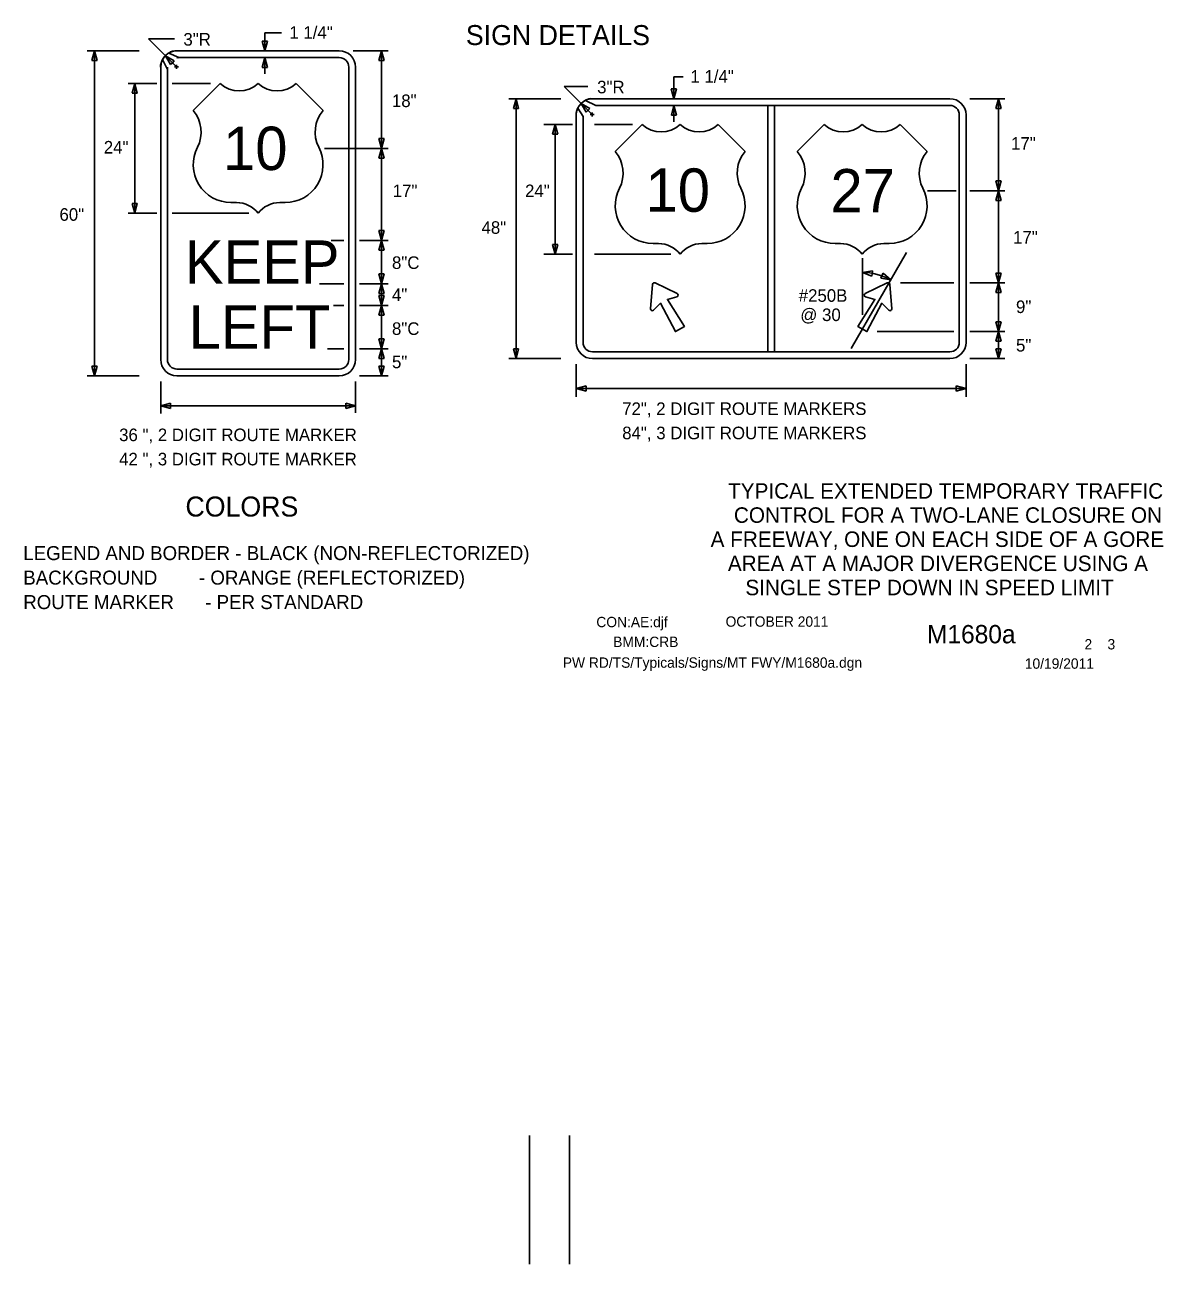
# Model space of a CAD drawing. Extents: x 16486 to 19505, y 5576 to 6998.
# Drawn here: x 17777 to 18460, y 5576 to 6320 of the extents above; entities that cross this region are included whole.
import ezdxf

# ---------------------------------------------------------------- set-up
doc = ezdxf.new("R2010")
doc.units = 0
for name, color, linetype in [('ALI_LEGAL_EX', 7, 'Continuous'), ('BORDER', 7, 'Continuous'), ('BORDER_SIGNAL_WO', 7, 'Continuous'), ('TRAFFIC_SIGNS_PR', 7, 'Continuous'), ('TYPICAL_EX', 7, 'Continuous'), ('TYPICAL_TEXT_DIMEN_PR', 7, 'Continuous')]:
    doc.layers.add(name, color=color, linetype=linetype)

msp = doc.modelspace()

# ---------------------------------------------------------------- linework, layer by layer
at = {"layer": 'ALI_LEGAL_EX'}
for p, q in [((18079.61, 5652.91), (18079.61, 5575.75)), ((18103.61, 5652.91), (18103.61, 5575.75))]:
    msp.add_line(p, q, dxfattribs=at)
at = {"layer": 'TRAFFIC_SIGNS_PR'}
for p, q in [((17860.3, 6300.32), (17859.29, 6298.82)), ((17869.08, 6299.88), (17862.99, 6302.62)), ((17867.88, 6303.94), (17965.38, 6303.94)), ((17858.13, 6118.69), (17858.13, 6294.19)), ((17859.32, 6298.74), (17862.19, 6292.7)), ((17862.19, 6294.19), (17862.19, 6118.69)), ((17965.38, 6299.88), (17867.88, 6299.88)), ((17971.06, 6118.69), (17971.06, 6294.19)), ((17975.13, 6294.19), (17975.13, 6118.69)), ((18119.35, 6271.19), (18113.12, 6274.21)), ((18117.4, 6275.24), (18331.9, 6275.24)), ((18117.4, 6275.24), (18331.9, 6275.24)), ((18119.34, 6271.18), (18222.62, 6271.18)), ((18331.9, 6271.18), (18119.34, 6271.18)), ((18222.62, 6271.18), (18222.62, 6123.31)), ((18226.68, 6271.18), (18226.68, 6123.31)), ((18226.68, 6271.18), (18331.9, 6271.18)), ((18107.65, 6265.49), (18107.65, 6128.99)), ((18107.65, 6128.99), (18107.65, 6265.49)), ((18108.57, 6269.5), (18111.71, 6264.46)), ((18111.71, 6264.44), (18111.71, 6128.99)), ((18111.71, 6264.44), (18111.71, 6128.99)), ((18337.59, 6265.49), (18337.59, 6219.74)), ((18337.59, 6128.99), (18337.59, 6265.49)), ((18341.65, 6265.49), (18341.65, 6128.99)), ((18341.65, 6265.49), (18341.65, 6128.99)), ((18337.59, 6219.74), (18337.59, 6128.99)), ((18152.25, 6149.1), (18153.4, 6163.82)), ((18154.91, 6164.69), (18168.23, 6158.33)), ((18294.38, 6164.69), (18281.07, 6158.33)), ((18297.05, 6149.1), (18295.9, 6163.82)), ((18117.4, 6123.31), (18331.9, 6123.31)), ((18117.4, 6119.24), (18331.9, 6119.24)), ((18331.9, 6119.24), (18117.4, 6119.24)), ((17867.88, 6113), (17965.38, 6113)), ((17965.38, 6108.94), (17867.88, 6108.94))]:
    msp.add_line(p, q, dxfattribs=at)
for points in [[(18119.34, 6271.18), (18119.32, 6271.19)], [(18111.71, 6264.46), (18111.71, 6264.44)], [(18168.07, 6156.36), (18162.34, 6154.78), (18172.56, 6138.61), (18167.16, 6135.49), (18158.27, 6152.43), (18154.04, 6148.26)], [(18281.23, 6156.36), (18286.96, 6154.78), (18276.74, 6138.61), (18282.14, 6135.49), (18291.03, 6152.43), (18295.26, 6148.26)]]:
    msp.add_lwpolyline(points, dxfattribs=at)
msp.add_lwpolyline([(18222.62, 6271.18), (18226.68, 6271.18), (18226.68, 6123.31), (18222.62, 6123.31)], close=True, dxfattribs=at)
for centre, radius, start, end in [((17867.88, 6294.19), 9.75, 90, 180), ((17867.29, 6296.37), 7.6, 85.58319, 124.53531), ((17965.38, 6294.19), 9.75, 0, 90), ((17865.16, 6294.78), 7.06, 145.86811, 184.82317), ((17856.73, 6293.45), 5.51, 352.24294, 7.75653), ((17868.48, 6304.31), 4.47, 262.2432, 277.7568), ((17965.38, 6294.19), 5.69, 0, 90), ((18117.4, 6265.49), 9.75, 90, 180), ((18117.4, 6265.49), 9.75, 90, 180), ((18116.72, 6268.68), 6.6, 84.11162, 123.06374), ((18118.34, 6278.36), 7.24, 277.81035, 278.05403), ((18331.9, 6265.49), 9.75, 0, 90), ((18331.9, 6265.49), 9.75, 0, 90), ((18331.9, 6265.49), 5.69, 0, 89.99421), ((18331.9, 6265.49), 5.69, 0, 90), ((18113.78, 6266.2), 6.17, 147.60925, 186.56283), ((18154.46, 6163.73), 1.06, 64.48226, 175.51774), ((18294.84, 6163.73), 1.06, 4.48226, 115.51774), ((18167.77, 6157.38), 1.06, 285.9885, 64.48226), ((18281.53, 6157.38), 1.06, 115.51774, 254.0115), ((18153.31, 6149.02), 1.06, 175.51775, 314.01151), ((18295.99, 6149.02), 1.06, 225.98849, 4.48225), ((18117.4, 6128.99), 9.75, 180, 270), ((18117.4, 6128.99), 9.75, 180, 270), ((18117.4, 6128.99), 5.69, 180, 270), ((18117.4, 6128.99), 5.69, 180, 270), ((18331.9, 6128.99), 9.75, 270, 0), ((18331.9, 6128.99), 5.69, 270, 0), ((18331.9, 6128.99), 9.75, 270, 0), ((18331.9, 6128.99), 5.69, 270, 0), ((17867.88, 6118.69), 9.75, 180, 270), ((17867.88, 6118.69), 5.69, 180, 270), ((17965.38, 6118.69), 5.69, 270, 0), ((17965.38, 6118.69), 9.75, 270, 0)]:
    msp.add_arc(centre, radius, start, end, dxfattribs=at)
at = {"layer": 'TYPICAL_EX'}
for p, q in [((17877.63, 6268.19), (17893.88, 6284.44)), ((17955.63, 6268.19), (17939.38, 6284.44)), ((18131.01, 6243.58), (18147.26, 6259.83)), ((18209.01, 6243.58), (18192.76, 6259.83)), ((18240.29, 6243.58), (18256.54, 6259.83)), ((18318.29, 6243.58), (18302.04, 6259.83)), ((17900.35, 6212.9), (17903.6, 6212.9)), ((17932.9, 6212.9), (17929.65, 6212.9)), ((18153.74, 6188.29), (18156.99, 6188.29)), ((18186.28, 6188.29), (18183.03, 6188.29)), ((18263.01, 6188.29), (18266.26, 6188.29)), ((18295.56, 6188.29), (18292.31, 6188.29))]:
    msp.add_line(p, q, dxfattribs=at)
for centre, radius, start, end in [((17905.25, 6296.28), 16.42, 226.14041, 313.85958), ((17928, 6296.28), 16.42, 226.14042, 313.85959), ((17862.23, 6255.18), 20.16, 333.09768, 40.19361), ((17971.03, 6255.18), 20.16, 139.80639, 206.90233), ((18158.64, 6271.67), 16.42, 226.14041, 313.85958), ((18181.39, 6271.67), 16.42, 226.14042, 313.85959), ((18267.91, 6271.67), 16.42, 226.14041, 313.85958), ((18290.66, 6271.67), 16.42, 226.14042, 313.85959), ((17900.4, 6235.63), 22.73, 152.6698, 269.90132), ((17932.86, 6235.63), 22.73, 270.09868, 27.3302), ((18115.61, 6230.57), 20.16, 333.09768, 40.19361), ((18224.41, 6230.57), 20.16, 139.80639, 206.90233), ((18224.89, 6230.57), 20.16, 333.09768, 40.19361), ((18333.69, 6230.57), 20.16, 139.80639, 206.90233), ((18153.78, 6211.02), 22.73, 152.6698, 269.90132), ((18186.24, 6211.02), 22.73, 270.09868, 27.3302), ((18263.06, 6211.02), 22.73, 152.6698, 269.90132), ((18295.52, 6211.02), 22.73, 270.09868, 27.3302), ((17903.65, 6196.62), 16.28, 37.1038, 90.13853), ((17929.61, 6196.62), 16.28, 89.86147, 142.8962), ((18157.03, 6172.01), 16.28, 37.1038, 90.13853), ((18182.99, 6172.01), 16.28, 89.86147, 142.8962), ((18266.31, 6172.01), 16.28, 37.1038, 90.13853), ((18292.27, 6172.01), 16.28, 89.86147, 142.8962)]:
    msp.add_arc(centre, radius, start, end, dxfattribs=at)
at = {"layer": 'TYPICAL_TEXT_DIMEN_PR'}
for p, q in [((17866.5, 6311.23), (17850.84, 6311.23)), ((17850.84, 6311.23), (17861.08, 6300.99)), ((17920.6, 6303.94), (17919.03, 6309.8)), ((17919.03, 6309.8), (17920.6, 6309.8)), ((17920.6, 6314.7), (17920.6, 6303.94)), ((17920.6, 6314.7), (17930.71, 6314.7)), ((17920.6, 6309.8), (17922.17, 6309.8)), ((17922.17, 6309.8), (17920.6, 6303.94)), ((17845.3, 6303.94), (17814, 6303.94)), ((17816.77, 6298.08), (17818.34, 6303.94)), ((17818.34, 6303.94), (17818.34, 6108.94)), ((17818.34, 6303.94), (17819.91, 6298.08)), ((17861.08, 6300.99), (17867.64, 6294.43)), ((17864.11, 6295.73), (17861.08, 6300.99)), ((17861.08, 6300.99), (17866.33, 6297.95)), ((17973.67, 6303.94), (17994.63, 6303.94)), ((17989.16, 6298.08), (17990.73, 6303.94)), ((17990.73, 6303.94), (17990.73, 6245.44)), ((17990.73, 6303.94), (17992.3, 6298.08)), ((17818.34, 6298.08), (17816.77, 6298.08)), ((17819.91, 6298.08), (17818.34, 6298.08)), ((17865.22, 6296.84), (17864.11, 6295.73)), ((17866.33, 6297.95), (17865.22, 6296.84)), ((17866.43, 6294.43), (17868.85, 6294.43)), ((17867.64, 6293.22), (17867.64, 6295.64)), ((17919.08, 6294.02), (17920.65, 6299.88)), ((17920.65, 6294.02), (17919.08, 6294.02)), ((17920.65, 6299.88), (17920.65, 6290.13)), ((17920.65, 6299.88), (17922.22, 6294.02)), ((17922.22, 6294.02), (17920.65, 6294.02)), ((17990.73, 6298.08), (17989.16, 6298.08)), ((17992.3, 6298.08), (17990.73, 6298.08)), ((18166.26, 6288.4), (18166.26, 6275.24)), ((18166.26, 6288.4), (18171.78, 6288.4)), ((17855.76, 6284.44), (17838.63, 6284.44)), ((17840.95, 6278.58), (17842.52, 6284.44)), ((17842.52, 6278.58), (17840.95, 6278.58)), ((17842.52, 6284.44), (17842.52, 6206.44)), ((17842.52, 6284.44), (17844.1, 6278.58)), ((17844.1, 6278.58), (17842.52, 6278.58)), ((17887.99, 6284.44), (17865.12, 6284.44)), ((18114.54, 6282.53), (18100.36, 6282.53)), ((18100.36, 6282.53), (18110.51, 6272.38)), ((18166.26, 6275.24), (18164.69, 6281.11)), ((18164.69, 6281.11), (18166.26, 6281.11)), ((18166.26, 6281.11), (18167.83, 6281.11)), ((18167.83, 6281.11), (18166.26, 6275.24)), ((18098.42, 6275.24), (18067.12, 6275.24)), ((18069.89, 6269.38), (18071.46, 6275.24)), ((18071.46, 6275.24), (18071.46, 6119.24)), ((18071.46, 6275.24), (18073.03, 6269.38)), ((18110.51, 6272.38), (18117.16, 6265.73)), ((18113.55, 6267.12), (18110.51, 6272.38)), ((18110.51, 6272.38), (18115.77, 6269.35)), ((18164.74, 6265.32), (18166.31, 6271.18)), ((18164.74, 6265.32), (18166.31, 6271.18)), ((18166.31, 6271.18), (18166.31, 6261.43)), ((18166.31, 6271.18), (18167.88, 6265.32)), ((18166.31, 6271.18), (18167.88, 6265.32)), ((18344.02, 6275.24), (18364.98, 6275.24)), ((18359.51, 6269.38), (18361.08, 6275.24)), ((18361.08, 6275.24), (18361.08, 6219.99)), ((18361.08, 6275.24), (18362.66, 6269.38)), ((18071.46, 6269.38), (18069.89, 6269.38)), ((18073.03, 6269.38), (18071.46, 6269.38)), ((18114.66, 6268.23), (18113.55, 6267.12)), ((18115.77, 6269.35), (18114.66, 6268.23)), ((18115.95, 6265.73), (18118.37, 6265.73)), ((18117.16, 6264.53), (18117.16, 6266.94)), ((18166.31, 6265.32), (18164.74, 6265.32)), ((18166.31, 6265.32), (18164.74, 6265.32)), ((18167.88, 6265.32), (18166.31, 6265.32)), ((18167.88, 6265.32), (18166.31, 6265.32)), ((18361.08, 6269.38), (18359.51, 6269.38)), ((18362.66, 6269.38), (18361.08, 6269.38)), ((18105.28, 6259.83), (18088.15, 6259.83)), ((18093.45, 6253.97), (18095.02, 6259.83)), ((18095.02, 6259.83), (18095.02, 6181.83)), ((18095.02, 6259.83), (18096.59, 6253.97)), ((18141.38, 6259.83), (18118.5, 6259.83)), ((17990.73, 6245.44), (17989.16, 6251.3)), ((17989.16, 6251.3), (17990.73, 6251.3)), ((17990.73, 6251.3), (17992.3, 6251.3)), ((17992.3, 6251.3), (17990.73, 6245.44)), ((18095.02, 6253.97), (18093.45, 6253.97)), ((18096.59, 6253.97), (18095.02, 6253.97)), ((17956.52, 6245.44), (17994.63, 6245.44)), ((17989.16, 6239.58), (17990.73, 6245.44)), ((17990.73, 6245.44), (17990.73, 6190.19)), ((17990.73, 6245.44), (17992.3, 6239.58)), ((17990.73, 6239.58), (17989.16, 6239.58)), ((17992.3, 6239.58), (17990.73, 6239.58)), ((18318.46, 6219.99), (18335.62, 6219.99)), ((18344.02, 6219.99), (18364.98, 6219.99)), ((18361.08, 6219.99), (18359.51, 6225.86)), ((18359.51, 6225.86), (18361.08, 6225.86)), ((18359.51, 6214.13), (18361.08, 6219.99)), ((18361.08, 6225.86), (18362.66, 6225.86)), ((18362.66, 6225.86), (18361.08, 6219.99)), ((18361.08, 6219.99), (18361.08, 6164.74)), ((18361.08, 6219.99), (18362.66, 6214.13)), ((17842.52, 6206.44), (17840.95, 6212.3)), ((17840.95, 6212.3), (17842.52, 6212.3)), ((17842.52, 6212.3), (17844.1, 6212.3)), ((17844.1, 6212.3), (17842.52, 6206.44)), ((18361.08, 6214.13), (18359.51, 6214.13)), ((18362.66, 6214.13), (18361.08, 6214.13)), ((17855.76, 6206.44), (17838.63, 6206.44)), ((17911.12, 6206.44), (17865.12, 6206.44)), ((17960.46, 6190.19), (17968.14, 6190.19)), ((17977.5, 6190.19), (17994.63, 6190.19)), ((17990.73, 6190.19), (17989.16, 6196.05)), ((17989.16, 6196.05), (17990.73, 6196.05)), ((17989.16, 6184.33), (17990.73, 6190.19)), ((17990.73, 6196.05), (17992.3, 6196.05)), ((17992.3, 6196.05), (17990.73, 6190.19)), ((17990.73, 6190.19), (17990.73, 6164.19)), ((17990.73, 6190.19), (17992.3, 6184.33)), ((17990.73, 6184.33), (17989.16, 6184.33)), ((17992.3, 6184.33), (17990.73, 6184.33)), ((18105.28, 6181.83), (18088.15, 6181.83)), ((18095.02, 6181.83), (18093.45, 6187.69)), ((18093.45, 6187.69), (18095.02, 6187.69)), ((18095.02, 6187.69), (18096.59, 6187.69)), ((18096.59, 6187.69), (18095.02, 6181.83)), ((18164.5, 6181.83), (18118.5, 6181.83)), ((18272.68, 6125.34), (18305.92, 6182.93)), ((18279.44, 6145.5), (18279.44, 6179.49)), ((17990.73, 6164.19), (17989.16, 6170.05)), ((17989.16, 6170.05), (17990.73, 6170.05)), ((17990.73, 6170.05), (17992.3, 6170.05)), ((17992.3, 6170.05), (17990.73, 6164.19)), ((18279.47, 6170.94), (18285.46, 6171.9)), ((18285.14, 6168.77), (18279.47, 6170.94)), ((18285.3, 6170.33), (18285.14, 6168.77)), ((18285.46, 6171.9), (18285.3, 6170.33)), ((18290.45, 6167.61), (18291.14, 6169.03)), ((18296.42, 6166.48), (18290.45, 6167.61)), ((18291.14, 6169.03), (18291.82, 6170.44)), ((18291.82, 6170.44), (18296.42, 6166.48)), ((18361.08, 6164.74), (18359.51, 6170.61)), ((18359.51, 6170.61), (18361.08, 6170.61)), ((18361.08, 6170.61), (18362.66, 6170.61)), ((18362.66, 6170.61), (18361.08, 6164.74)), ((17953.44, 6164.19), (17968.14, 6164.19)), ((17977.5, 6164.19), (17994.63, 6164.19)), ((17989.16, 6158.33), (17990.73, 6164.19)), ((17990.73, 6164.19), (17990.73, 6151.19)), ((17990.73, 6164.19), (17992.3, 6158.33)), ((18302.39, 6164.74), (18334.26, 6164.74)), ((18344.02, 6164.74), (18364.98, 6164.74)), ((18359.51, 6158.88), (18361.08, 6164.74)), ((18361.08, 6164.74), (18361.08, 6135.49)), ((18361.08, 6164.74), (18362.66, 6158.88)), ((17990.73, 6158.33), (17989.16, 6158.33)), ((17990.73, 6151.19), (17989.16, 6157.05)), ((17989.16, 6157.05), (17990.73, 6157.05)), ((17992.3, 6158.33), (17990.73, 6158.33)), ((17990.73, 6157.05), (17992.3, 6157.05)), ((17992.3, 6157.05), (17990.73, 6151.19)), ((18361.08, 6158.88), (18359.51, 6158.88)), ((18362.66, 6158.88), (18361.08, 6158.88)), ((17961.79, 6151.19), (17968.14, 6151.19)), ((17977.5, 6151.19), (17994.63, 6151.19)), ((17989.16, 6145.33), (17990.73, 6151.19)), ((17990.73, 6145.33), (17989.16, 6145.33)), ((17990.73, 6151.19), (17990.73, 6125.19)), ((17990.73, 6151.19), (17992.3, 6145.33)), ((17992.3, 6145.33), (17990.73, 6145.33)), ((18361.08, 6135.49), (18359.51, 6141.36)), ((18359.51, 6141.36), (18361.08, 6141.36)), ((18361.08, 6141.36), (18362.66, 6141.36)), ((18362.66, 6141.36), (18361.08, 6135.49)), ((17990.73, 6125.19), (17989.16, 6131.05)), ((17989.16, 6131.05), (17990.73, 6131.05)), ((17990.73, 6131.05), (17992.3, 6131.05)), ((17992.3, 6131.05), (17990.73, 6125.19)), ((18288.26, 6135.49), (18334.26, 6135.49)), ((18344.02, 6135.49), (18364.98, 6135.49)), ((18359.51, 6129.63), (18361.08, 6135.49)), ((18361.08, 6129.63), (18359.51, 6129.63)), ((18361.08, 6135.49), (18361.08, 6119.24)), ((18361.08, 6135.49), (18362.66, 6129.63)), ((18362.66, 6129.63), (18361.08, 6129.63)), ((17958.29, 6125.19), (17968.14, 6125.19)), ((17977.5, 6125.19), (17994.63, 6125.19)), ((17989.16, 6119.33), (17990.73, 6125.19)), ((17990.73, 6125.19), (17990.73, 6108.94)), ((17990.73, 6125.19), (17992.3, 6119.33)), ((18071.46, 6119.24), (18069.89, 6125.11)), ((18069.89, 6125.11), (18071.46, 6125.11)), ((18071.46, 6125.11), (18073.03, 6125.11)), ((18073.03, 6125.11), (18071.46, 6119.24)), ((18361.08, 6119.24), (18359.51, 6125.11)), ((18359.51, 6125.11), (18361.08, 6125.11)), ((18361.08, 6125.11), (18362.66, 6125.11)), ((18362.66, 6125.11), (18361.08, 6119.24)), ((17818.34, 6108.94), (17816.77, 6114.8)), ((17816.77, 6114.8), (17818.34, 6114.8)), ((17818.34, 6114.8), (17819.91, 6114.8)), ((17819.91, 6114.8), (17818.34, 6108.94)), ((17990.73, 6119.33), (17989.16, 6119.33)), ((17990.73, 6108.94), (17989.16, 6114.8)), ((17989.16, 6114.8), (17990.73, 6114.8)), ((17992.3, 6119.33), (17990.73, 6119.33)), ((17990.73, 6114.8), (17992.3, 6114.8)), ((17992.3, 6114.8), (17990.73, 6108.94)), ((18098.42, 6119.24), (18067.12, 6119.24)), ((18107.65, 6115.9), (18107.65, 6096.34)), ((18341.65, 6115.9), (18341.65, 6096.34)), ((18344.02, 6119.24), (18361.15, 6119.24)), ((18344.02, 6119.24), (18364.98, 6119.24)), ((18344.02, 6119.24), (18361.15, 6119.24)), ((17845.3, 6108.94), (17814, 6108.94)), ((17977.5, 6108.94), (17994.63, 6108.94)), ((17858.13, 6105.6), (17858.13, 6086.24)), ((17975.13, 6105.6), (17975.13, 6086.7)), ((18107.65, 6101.27), (18113.51, 6102.84)), ((18107.65, 6101.27), (18341.65, 6101.27)), ((18113.51, 6099.7), (18107.65, 6101.27)), ((18113.51, 6102.84), (18113.51, 6101.27)), ((18113.51, 6101.27), (18113.51, 6099.7)), ((18335.79, 6101.27), (18335.79, 6102.84)), ((18335.79, 6102.84), (18341.65, 6101.27)), ((18341.65, 6101.27), (18335.79, 6099.7)), ((18335.79, 6099.7), (18335.79, 6101.27)), ((17858.13, 6090.97), (17863.99, 6092.54)), ((17863.99, 6092.54), (17863.99, 6090.97)), ((17969.27, 6090.97), (17969.27, 6092.54)), ((17969.27, 6092.54), (17975.13, 6090.97)), ((17858.13, 6090.97), (17975.13, 6090.97)), ((17863.99, 6089.4), (17858.13, 6090.97)), ((17863.99, 6090.97), (17863.99, 6089.4)), ((17975.13, 6090.97), (17969.27, 6089.4)), ((17969.27, 6089.4), (17969.27, 6090.97))]:
    msp.add_line(p, q, dxfattribs=at)
msp.add_arc((18279.63, 6136.5), 34.39, 60.74521, 90.32117, dxfattribs=at)

# ---------------------------------------------------------------- texts
at = {"layer": 'BORDER'}
for s, p in [('TYPICAL EXTENDED TEMPORARY TRAFFIC', (18198.78, 6035.19)), ('CONTROL FOR A TWO-LANE CLOSURE ON', (18202.28, 6020.7)), ('A FREEWAY, ONE ON EACH SIDE OF A GORE', (18188.3, 6006.21)), ('AREA AT A MAJOR DIVERGENCE USING A', (18198.66, 5991.71)), ('SINGLE STEP DOWN IN SPEED LIMIT', (18209.16, 5977.22))]:
    msp.add_text(s, height=9.3, dxfattribs=at).set_placement(p)
at = {"layer": 'BORDER_SIGNAL_WO'}
for s, height, p in [('CON:AE:djf  ', 6.2, (18119.69, 5958.06)), ('    OCTOBER 2011    ', 6.2, (18188.08, 5958.34)), ('    M1680a   ', 11, (18301.86, 5948.38)), ('BMM:CRB   ', 6.2, (18129.81, 5946.17)), (' 2    3 ', 6.2, (18410.45, 5944.7)), ('PW RD/TS/Typicals/Signs/MT FWY/M1680a.dgn      ', 6.2, (18099.55, 5933.71)), ('10/19/2011    ', 6.2, (18376.93, 5933.13))]:
    msp.add_text(s, height=height, dxfattribs=at).set_placement(p)
at = {"layer": 'TRAFFIC_SIGNS_PR'}
for s, p in [('10', (17895.6, 6232.44)), ('10', (18149.25, 6207.37)), ('27', (18260.26, 6207.01)), ('KEEP', (17872.73, 6164.19)), ('LEFT', (17874.97, 6125.19))]:
    msp.add_text(s, height=26, dxfattribs=at).set_placement(p)
at = {"layer": 'TYPICAL_TEXT_DIMEN_PR'}
for s, height, p in [('1 1/4"', 7.55, (17935.4, 6311.2)), ('SIGN DETAILS', 12, (18041.35, 6307.41)), ('3"R', 7.55, (17871.77, 6307.1)), ('3"R', 7.55, (18120.18, 6278.45)), ('1 1/4"', 7.55, (18176.18, 6284.82)), ('18"', 7.55, (17996.97, 6270.21)), ('24"', 7.55, (17823.97, 6242.33)), ('17"', 7.55, (18368.66, 6244.6)), ('17"', 7.55, (17997.43, 6216.16)), ('24"', 7.55, (18076.88, 6216.16)), ('60"', 7.55, (17797.37, 6201.96)), ('48"', 7.55, (18050.76, 6194.14)), ('17"', 7.55, (18369.86, 6188.24)), ('8"C', 7.55, (17997, 6173.05)), ('4" ', 7.55, (17997, 6153.79)), ('#250B', 7.55, (18241.21, 6153.34)), ('9"', 7.55, (18371.64, 6146.59)), ('@ 30', 7.55, (18242.15, 6141.78)), ('8"C', 7.55, (17997, 6133.46)), ('5"', 7.55, (18371.64, 6123.49)), ('5" ', 7.55, (17997, 6113.49)), ('72", 2 DIGIT ROUTE MARKERS', 7.55, (18135.23, 6085.41)), ('36 ", 2 DIGIT ROUTE MARKER', 7.55, (17833.18, 6069.71)), ('84", 3 DIGIT ROUTE MARKERS', 7.55, (18135.23, 6070.86)), ('42 ", 3 DIGIT ROUTE MARKER', 7.55, (17833.18, 6055.16)), ('COLORS', 12, (17873, 6024.47)), ('LEGEND AND BORDER - BLACK (NON-REFLECTORIZED)', 8.4, (17775.62, 5998.31)), ('BACKGROUND        - ORANGE (REFLECTORIZED)', 8.4, (17775.62, 5983.61)), ('ROUTE MARKER      - PER STANDARD', 8.4, (17775.62, 5968.91))]:
    msp.add_text(s, height=height, dxfattribs=at).set_placement(p)

doc.saveas('drawing.dxf')
